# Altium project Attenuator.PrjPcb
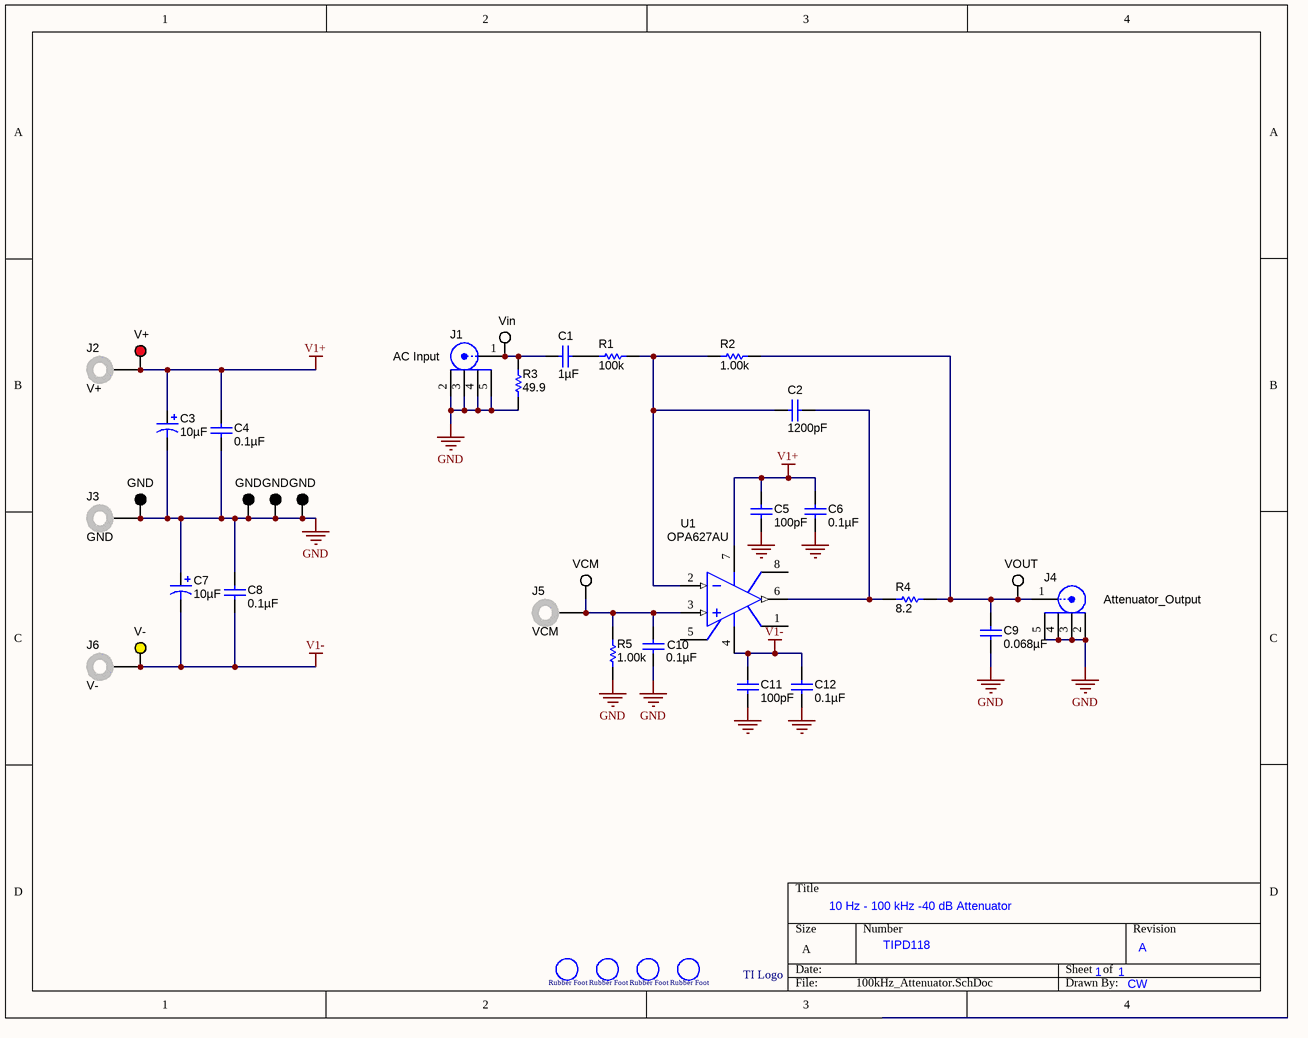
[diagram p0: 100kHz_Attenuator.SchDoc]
CopyrightYear: 2012; PCB_CopperRev: 001; PCB_SilkRev: REV A; PRJ_BasePN: xxxxxx; PRJ_Customer: Public Release; PRJ_Title: Change me in menu Project|Project Options|Parameters; SCH_Rev: X1; TechSupport: http://www.ti.com/support
1 sheet, 38 parts. Net scope: global (net labels, ports and power ports of the same name join across sheets).
Board file: PCB2.PcbDoc

## Sheet 100kHz_Attenuator.SchDoc
size A; PageSetup: Record=PageOptions|CenterHorizontal=True|CenterVertical=True|PrintScale=1.09|XCorrection=1.00|YCorrection=1.00|PrintKind=1|BorderSize=5000000|LeftOffset=0|BottomOffset=0|Orientation=2|PaperLength=1000|PaperWidth=1000|Scale=100|PaperSource=15|PrintQuality=600|MediaType=1|DitherType=10|PaperKind=11x17|PrintScaleMode=1

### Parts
C1  ValueDisplayed: 1µF  [1206]  (hidden comment: GRM31CR72A105KA01L)
C2  ValueDisplayed: 1200pF  [0805_HV]  (hidden comment: 08055A122JAT2A)
C3  ValueDisplayed: 10µF  [7343-43]  (hidden comment: TPSE106K050R0400)
C4  ValueDisplayed: 0.1µF  [0805]  (hidden comment: GRM21BR71H104KA01L)
C5  ValueDisplayed: 100pF  [0805]  (hidden comment: GRM2165C1H101JA01D)
C6  ValueDisplayed: 0.1µF  [0805]  (hidden comment: GRM21BR71H104KA01L)
C7  ValueDisplayed: 10µF  [7343-43]  (hidden comment: TPSE106K050R0400)
C8  ValueDisplayed: 0.1µF  [0805]  (hidden comment: GRM21BR71H104KA01L)
C9  ValueDisplayed: 0.068µF  [1206]  (hidden comment: GRM31C5C1H683JA01L)
C10  ValueDisplayed: 0.1µF  [1206]  (hidden comment: CGJ5L2C0G1H104J160AA)
C11  ValueDisplayed: 100pF  [0805]  (hidden comment: GRM2165C1H101JA01D)
C12  ValueDisplayed: 0.1µF  [0805]  (hidden comment: GRM21BR71H104KA01L)
F1  (no value)  [Rubber_Foot]  (no BOM)
F2  (no value)  [Rubber_Foot]  (no BOM)
F3  (no value)  [Rubber_Foot]  (no BOM)
F4  (no value)  [Rubber_Foot]  (no BOM)
J1  142-0701-201  [Johnson_142-0701-20x]  (value not drawn)
J2  V+  [Keystone_575-4]
J3  GND  [Keystone_575-4]
J4  142-0701-201  [Johnson_142-0701-20x]  (value not drawn)
J5  VCM  [Keystone_575-4]
J6  V-  [Keystone_575-4]
R1  value 100k  [0805_HV]  (hidden comment: RG2012P-104-B-T5)
R2  value 1.00k  [0805_HV]  (hidden comment: RG2012P-102-B-T5)
R3  value 49.9  [0805]  (hidden comment: 49.9R)
R4  value 8.2  [0805_HV]  (hidden comment: RJ0805FRE078R2L)
R5  value 1.00k  [0805_HV]  (hidden comment: CRCW08051K00FKEA)
TI1  Texas Instruments logo  [TI LOGO]  (value not drawn)  (no BOM)
TP1  Vin  [Keystone5002]
TP2  V+  [Keystone5000]
TP3  GND  [Keystone5001]
TP4  GND  [Keystone5001]
TP5  GND  [Keystone5001]
TP6  GND  [Keystone5001]
TP7  VCM  [Keystone5002]
TP8  VOUT  [Keystone5002]
TP9  V-  [Keystone5004]
U1  OPA627AU  [182H_N]

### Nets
GND: C3.2(-) C4.2 C5.2 C6.2 C7.1(+) C8.1 C9.2 C10.2 C11.2 C12.2 J1.2 J1.3 J1.4 J1.5 J3.1 J4.2 J4.3 J4.4 J4.5 R3.2 R5.1 TP3.1 TP4.1 TP5.1 TP6.1
V1+: C3.1(+) C4.1 C5.1 C6.1 J2.1 TP2.1 U1.7(V+)
V1-: C7.2(-) C8.2 C11.1 C12.1 J6.1 TP9.1 U1.4(V-)
NetC1_1: C1.1 R1.1
NetC1_2: C1.2 J1.1 R3.1 TP1.1
NetC2_1: C2.1 R4.1 U1.6(OUT)
NetC2_2: C2.2 R1.2 R2.1 U1.2(IN-)
NetC9_1: C9.1 J4.1 R2.2 R4.2 TP8.1
NetC10_1: C10.1 J5.1 R5.2 TP7.1 U1.3(IN+)

Not connected (* = marked no-connect by the designer): U1 1(OS_TRIM) 5(OS_TRIM) 8(NC)

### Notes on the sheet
- (near J1) AC Input
- (near J4) Attenuator_Output
- 10 Hz - 100 kHz -40 dB Attenuator
- TIPD118
- 1
- A
- CW

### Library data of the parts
C1 = GRM31CR72A105KA01L: CAP, CERM, 1uF, 100V, +/-10%, X7R, 1206; Manufacturer: MuRata; Polarized: N; CompType: Capacitor; U/M: EA; Cap_F: 0.000001; Tolerance_%: 10; VDC_V: 100; TaMin_C: -55; TaMax_C: 125; Cap_Case: 2220
C2 = 08055A122JAT2A: CAP, CERM, 1200pF, 50V, +/-5%, C0G/NP0, 0805; Manufacturer: AVX; Polarized: N; CompType: Capacitor; U/M: EA; Cap_F: 0.0000000012; Tolerance_%: 5; ESR_Ohm: 0.104; Value1: 0.104 ohm; VDC_V: 50; TaMin_C: -55; TaMax_C: 125; Cap_Case: 0805
C3 C7 = TPSE106K050R0400: CAP, TANT, 10uF, 50V, +/-10%, 0.4 ohm, 7343-43 SMD; Manufacturer: AVX; Polarized: Y; CompType: Capacitor; U/M: EA; Cap_F: 0.00001; Tolerance_%: 10; Value1: 0.4 ohm; VDC_V: 50; ESR_Ohm: 0.4; IRMS_A: 0.578; TaMin_C: -55; TaMax_C: 125; Cap_Case: E
C4 C6 C8 C12 = GRM21BR71H104KA01L: CAP, CERM, 0.1uF, 50V, +/-10%, X7R, 0805; Manufacturer: MuRata; Polarized: N; CompType: Capacitor; U/M: EA; Cap_F: 0.0000001; Tolerance_%: 10; VDC_V: 50; TaMin_C: -55; TaMax_C: 125
C5 C11 = GRM2165C1H101JA01D: CAP, CERM, 100pF, 50V, +/-5%, C0G/NP0, 0805; Manufacturer: MuRata; Polarized: N; CompType: Capacitor; U/M: EA; Cap_F: 0.0000000001; Tolerance_%: 5; VDC_V: 50; TaMin_C: -55; TaMax_C: 125
C9 = GRM31C5C1H683JA01L: CAP, CERM, 0.068uF, 50V, +/-5%, C0G/NP0, 1206; Manufacturer: MuRata; Polarized: N; CompType: Capacitor; U/M: EA; Cap_F: 0.000000068; Tolerance_%: 5; ESR_Ohm: 0.01; Value1: 0.01 ohm; VDC_V: 50; IRMS_A: 0.9; TaMin_C: -55; TaMax_C: 125
C10 = 12065C104KAT2A: CAP CER 0.1UF 50V 5% NP0 1206; Manufacturer: TDK Corporation; Polarized: N; CompType: Capacitor; U/M: EA; Cap_F: 0.0000001; Tolerance_%: 10; ESR_Ohm: 0.037; VDC_V: 50; TempCo: X7R; TaMin_C: -55; TaMax_C: 125
F1-F4 = SJ61A1: BUMPON CYLINDRICAL .312X.200 BLK; Manufacturer: 3M; CompType: Rubber Mounting Feet; SymbolCreator: use LDAP id; U/M: EA, IN, or GM
J1 J4 = 142-0701-201: Connector, TH, SMA; Manufacturer: Emerson Network Power; U/M: EA
J2 J3 J5 J6 = 575-4: Standard Banana Jack, Uninsulated, 5.5mm; Manufacturer: Keystone; CompType: Connector; U/M: EA
R1 = RG2012P-104-B-T5: RES, 100k ohm, 0.1%, 0.125W, 0805; Manufacturer: Susumu Co Ltd; CompType: Resistor; Res_ohm: 100000; Tolerance_%: 0.1; Power_W: 0.125; VDC_V: 100; TempCo: 25 ppm/C; EIA_Code: E192; U/M: EA
R2 = RG2012P-102-B-T5: RES, 1.00k ohm, 0.1%, 0.125W, 0805; Manufacturer: Susumu Co Ltd; CompType: Resistor; Res_ohm: 1000; Value_Code: 1k00; Tolerance_%: 0.1; Power_W: 0.125; VDC_V: 100; TempCo: 25 ppm/C; EIA_Code: E192; U/M: EA
R3 = CRCW080549R9FKEA: RES 49.9 OHM 0.20W 0.1% 0805; PartNumber: PAT0805E49R9BST1; Manufacturer: Vishay Thin Film; CompType: Resistor; Value_Code: 49R9; Tolerance_%: 0.1; Power_W: 0.2; TempCo: 25ppm; EIA_Code: E96; U/M: EA
R4 = CRCW08058R20JNEA: RES 8.2 OHM 1/10W 1% 0805 SMD; Manufacturer: Yageo; CompType: Resistor; Value_Code: 8R20; Tolerance_%: 5; Power_W: 0.125; Value2: 0.125W; VDC_V: 150; TempCo: 50 ppm/C; EIA_Code: E24; U/M: EA
R5 = CRCW08051K00FKEA: RES, 1.00k ohm, 1%, 0.125W, 0805; Manufacturer: Vishay-Dale; CompType: Resistor; Res_ohm: 1000; Value_Code: 1k00; Tolerance_%: 1; Power_W: 0.125; VDC_V: 150; TempCo: 100 ppm/C; EIA_Code: E96; U/M: EA
TI1 = TI LOGO: TI BUG
TP1 TP7 TP8 = 5002: Test Point, TH, Miniature, White; Manufacturer: Keystone; CompType: Test Point Loop; U/M: EA
TP2 = 5000: Test Point, TH, Miniature, Red; Manufacturer: Keystone; CompType: Test Point Loop; U/M: EA
TP3-TP6 = 5001: Test Point, TH, Miniature, Black; Manufacturer: Keystone; CompType: Test Point Loop; U/M: EA
TP9 = 5004: Test Point, TH, Miniature, Yellow; Manufacturer: Keystone; CompType: Test Point Loop; U/M: EA
U1 = OPA627AU: Precision High-Speed Difet Operational Amplifiers; Note: Pin 8 is No internal Connection (NC) pin.

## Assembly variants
-100A: all parts fitted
